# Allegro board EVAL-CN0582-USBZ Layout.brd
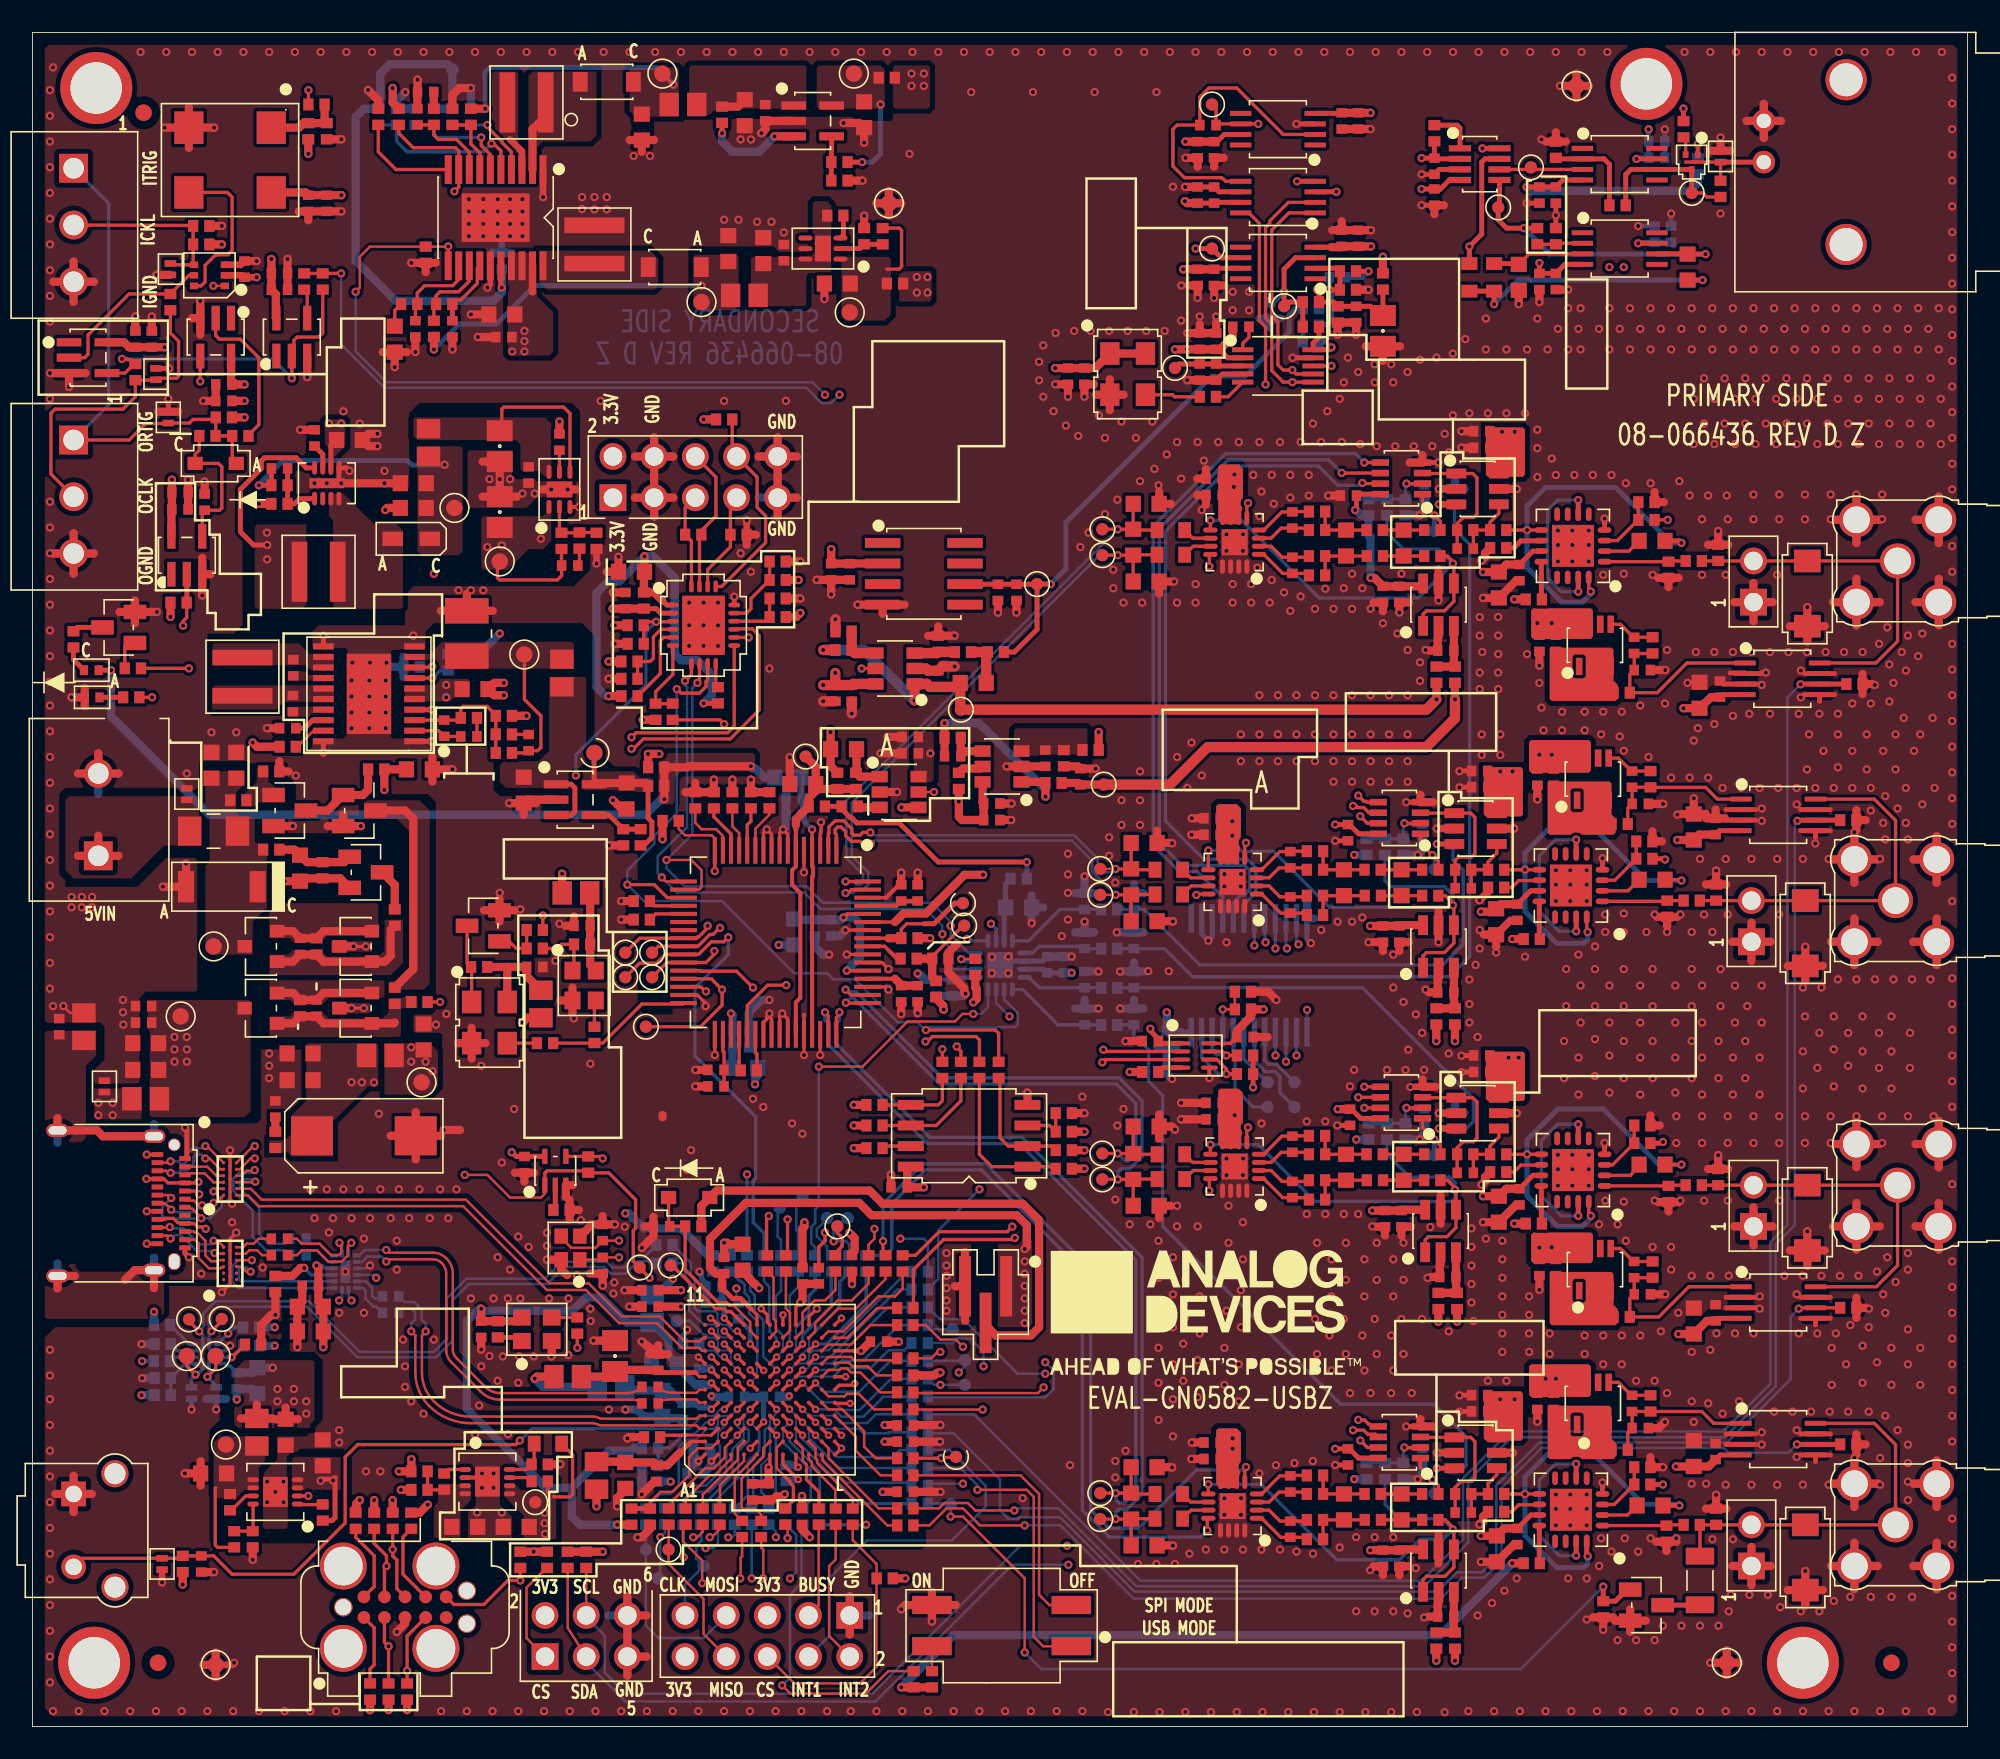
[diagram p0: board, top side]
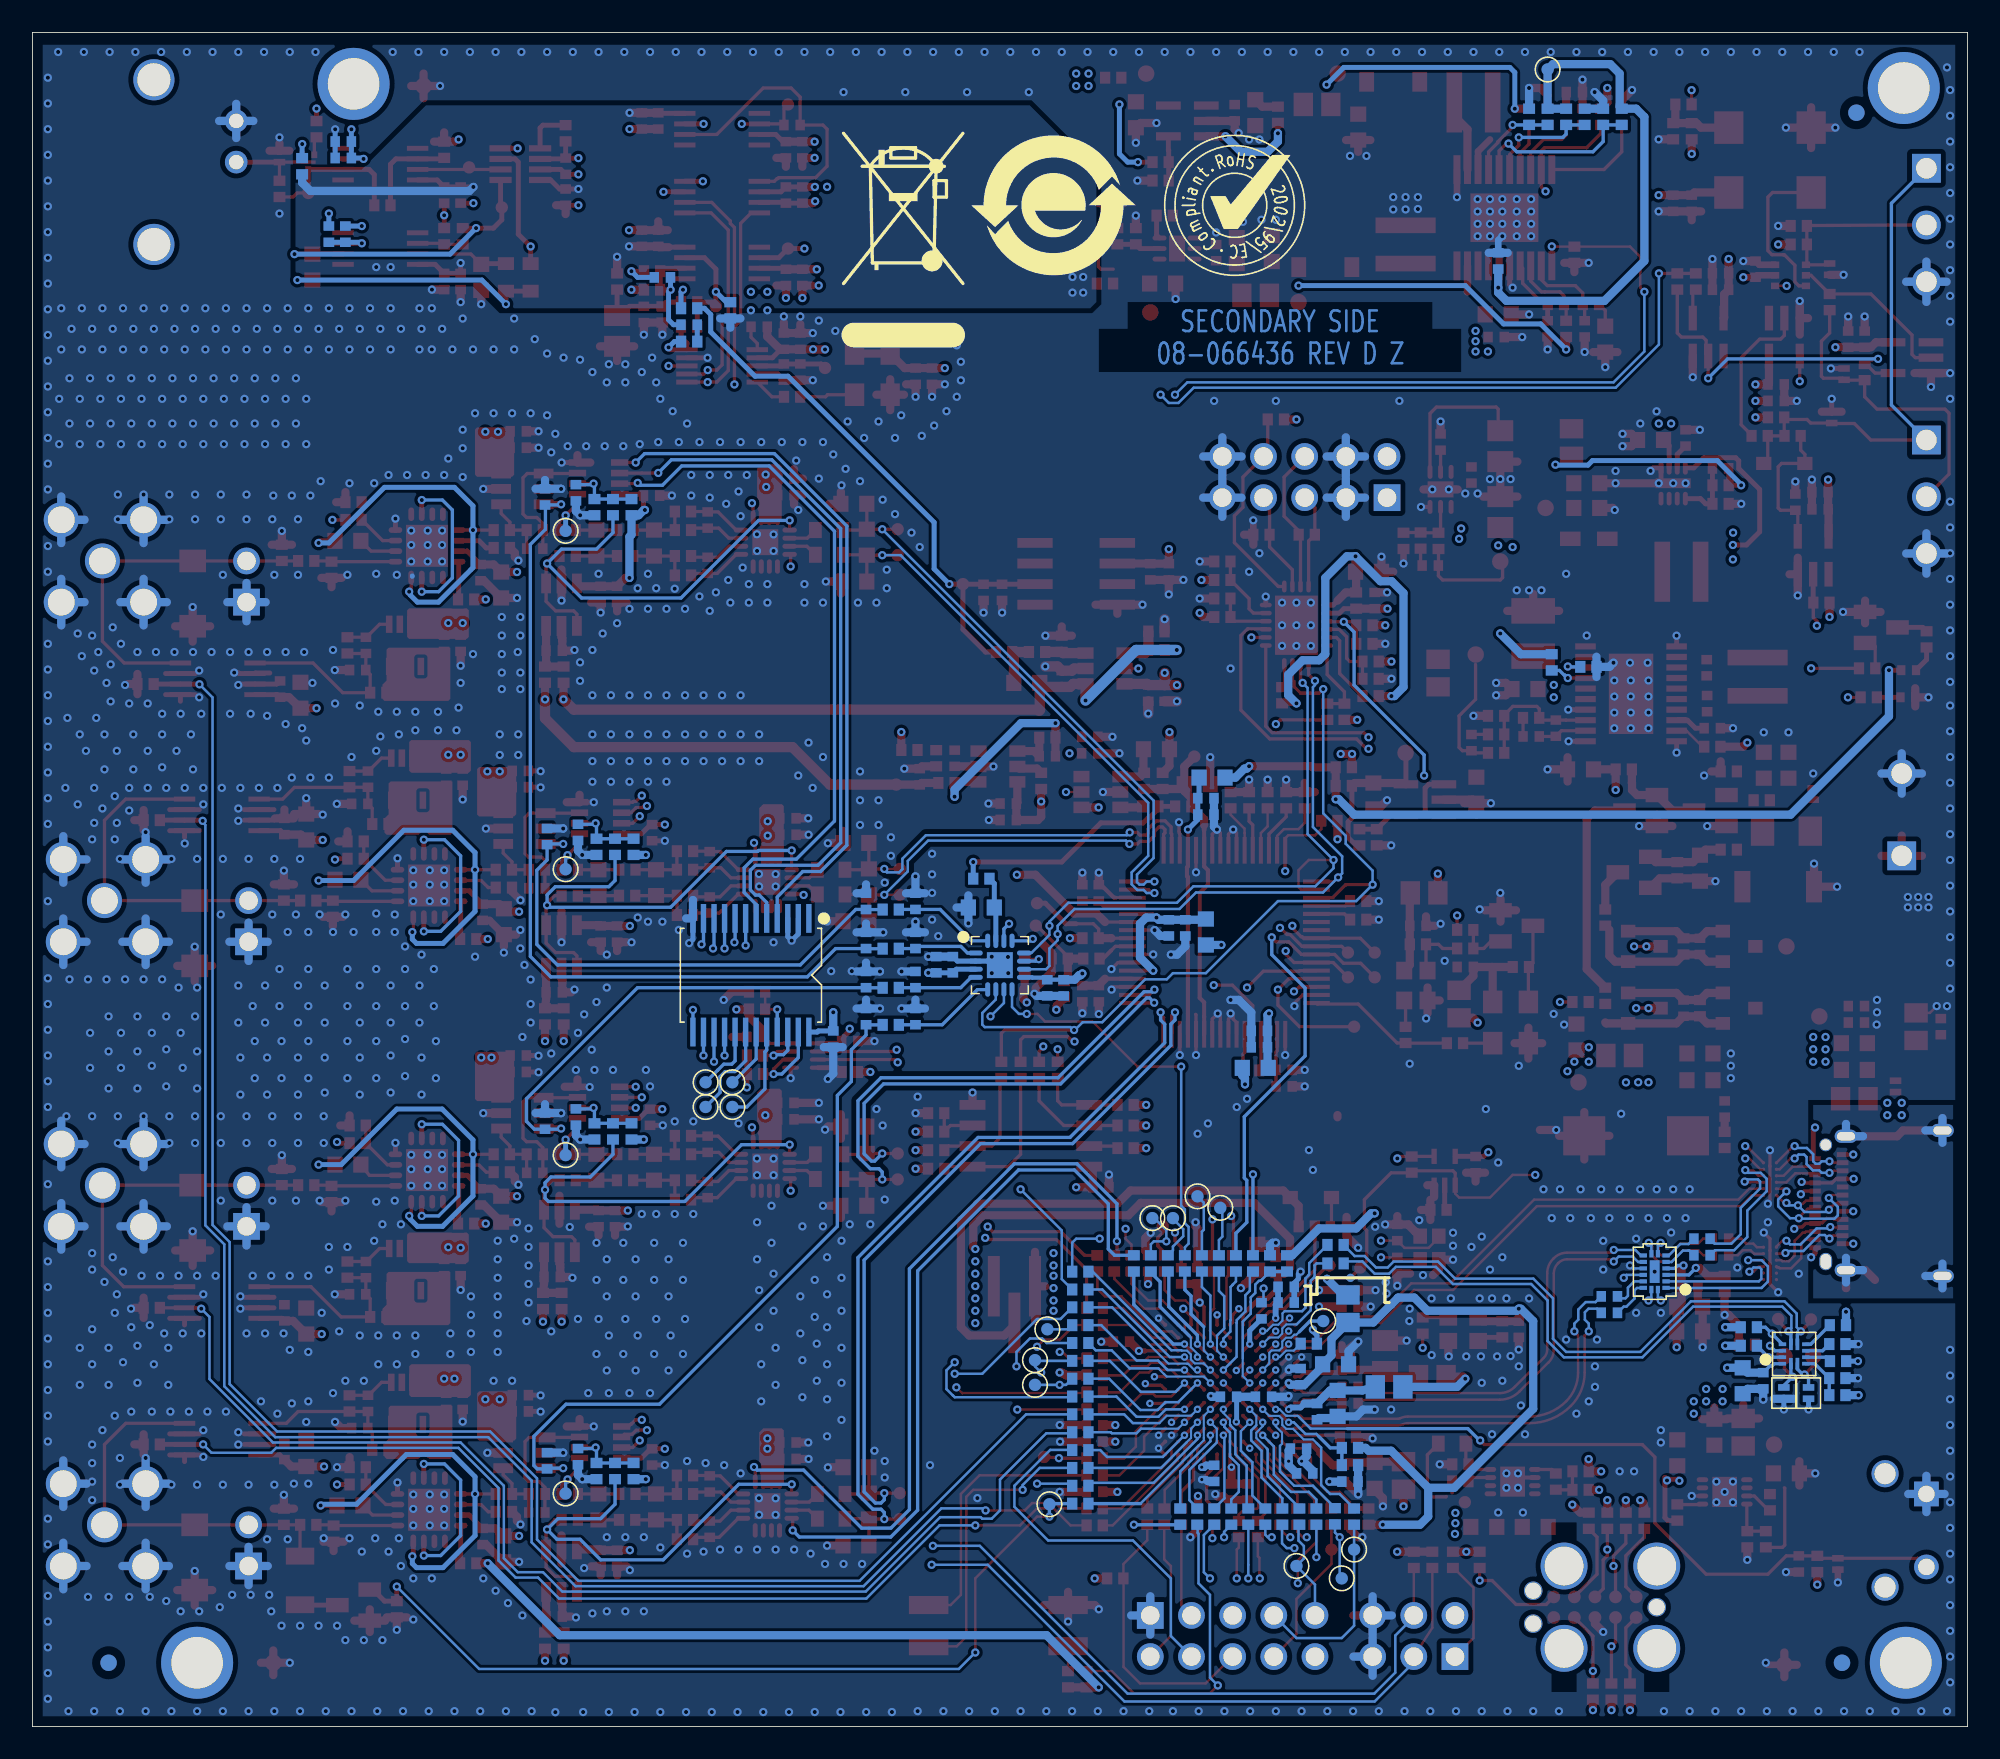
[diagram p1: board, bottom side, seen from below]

Outline 119.38 x 104.52 mm; copper layers: TOP, L2_GND, L3_SIG, L4_SIG, L5_GND, BOTTOM. Coordinates in mm from the lower left corner of the outline.
Outline path: 0,104.52 0,0 119.38,0 119.38,104.52 0,104.52

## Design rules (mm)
constraint set DEFAULT: min track width 0.152
net group CH0_OUT: nets CH0_OUT_N CH0_OUT_P
net group CH1_OUT: nets CH1_OUT_N CH1_OUT_P
net group CH2_OUT: nets CH2_OUT_N CH2_OUT_P
net group CH3_OUT: nets CH3_OUT_N CH3_OUT_P
net group CON_D: nets CON_DN CON_DP
net group CON_RX1: nets CON_RX1_N CON_RX1_P
net group CON_RX2: nets CON_RX2_N CON_RX2_P
net group CON_TX1: nets CON_TX1_N CON_TX1_P
net group CON_TX2: nets CON_TX2_N CON_TX2_P
net group DP1: nets SS_DM SS_DP
net group DP3: nets SS_TX_M SS_TX_P
net group DP4: nets UNNAMED_29_CAP_I53_N1 UNNAMED_29_CAP_I54_N1
net group RX1: nets RX1_N RX1_P
net group RX2: nets RX2_N RX2_P
net group SS_RX_M: nets SS_RX_M UNNAMED_29_CAP_I209_N2
net group SS_RX_P: nets SS_RX_P UNNAMED_29_CAP_I208_N2
net group TX1_N: nets TX1_N UNNAMED_22_CAP_I400_N1
net group TX1_P: nets TX1_P UNNAMED_22_CAP_I401_N1
net group TX2_N: nets TX2_N UNNAMED_22_CAP_I403_N1
net group TX2_P: nets TX2_P UNNAMED_22_CAP_I402_N1

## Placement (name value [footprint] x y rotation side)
A1  ADA4099-1HUJZ  [TSOT23_6]  89.15 37.85 270 top
A2  ADA4099-1HUJZ  [TSOT23_6]  89.03 16.89 270 top
A3  ADA4099-1HUJZ  [TSOT23_6]  89.15 76.36 270 top
A4  ADA4099-1HUJZ  [TSOT23_6]  89.03 55.4 270 top
A5  ADA4522-1ARMZ  [MSOP8]  97.92 91.19 270 top
A6  ADA4807-1ARJZ  [SOT23_6-2]  53.47 57.66 270 top
A7  ADA4522-1ARMZ  [MSOP8]  76.84 90.3 90 top
A8  ADA4522-1ARMZ  [MSOP8]  76.84 98.55 90 top
A9  ADA4807-1ARJZ  [SOT23_6-2]  53.21 65.28 90 top
A10  LTC6910-1HTS8#TRMPBF  [TSOT-8]  84.45 77.01 90 top
A11  LTC6910-1HTS8#TRMPBF  [TSOT-8]  84.33 56.05 90 top
A12  LTC6910-1HTS8#TRMPBF  [TSOT-8]  84.45 38.5 90 top
A13  LTC6910-1HTS8#TRMPBF  [TSOT-8]  84.33 17.54 90 top
A14  ADA4522-1ARMZ  [MSOP8]  97.92 96.39 270 top
A15  ADA4807-1ARJZ  [SOT23_6-2]  59.82 59.23 90 top
A16  ADA4099-1HUJZ  [TSOT23_6]  86.74 48.13 0 top
A17  ADA4099-1HUJZ  [TSOT23_6]  86.74 69.22 0 top
A18  ADA4099-1HUJZ  [TSOT23_6]  86.87 30.58 0 top
A19  ADA4099-1HUJZ  [TSOT23_6]  86.74 9.62 0 top
C1  0.1uF  [C0402]  1.65 43.18 90 top
C2  4.7uF  [C0603]  6.98 40.51 0 top
C3  1uF  [C0603]  6.98 42.16 0 top
C4  1000pF  [C0402]  64.91 48.5 270 bottom
C5  1000pF  [C0402]  64.91 46.09 270 bottom
C6  1000pF  [C0402]  67.95 48.5 270 bottom
C7  1000pF  [C0402]  67.95 46.09 270 bottom
C8  1000pF  [C0402]  64.91 43.8 270 bottom
C9  1000pF  [C0402]  64.91 50.91 270 bottom
C10  1000pF  [C0402]  67.95 43.8 270 bottom
C11  1000pF  [C0402]  67.95 50.91 270 bottom
C12  0.1uF  [C0402]  30.99 46.86 0 top
C13  0.1uF  [C0402]  33.91 49.4 180 top
C14  0.1uF  [C0402]  80.77 91.82 90 top
C15  10uF  [C0402]  81.79 91.82 270 top
C16  1uF  [C0402]  36.58 69.47 270 top
C17  4.7uF  [C0603]  36.96 71.25 180 top
C18  22uF  [C0603]  43.82 28.96 270 top
C19  0.1uF  [C0402]  38.1 26.92 180 top
C20  0.01uF  [C0402]  53.85 14.49 180 top
C21  0.01uF  [C0402]  38.1 25.91 0 top
C22  0.1uF  [C0402]  50.56 28.58 90 top
C23  0.01uF  [C0402]  46.48 15.62 90 bottom
C24  0.1uF  [C0402]  53.85 18.58 0 top
C25  0.1uF  [C0402]  92.96 28.32 270 top
C26  0.1uF  [C0402]  92.84 20.07 270 top
C27  10uF  [C0402]  98.81 28.19 90 top
C28  10uF  [C0402]  98.68 19.94 90 top
C29  0.1uF  [C0402]  93.98 28.32 270 top
C30  0.1uF  [C0402]  93.85 20.07 270 top
C31  0.1uF  [C0402]  99.31 26.67 0 top
C32  0.1uF  [C0402]  99.19 18.41 0 top
C33  68pF  [C0402]  88.39 34.16 180 top
C34  68pF  [C0402]  88.27 13.21 180 top
C35  0.1uF  [C0402]  89.41 40.39 180 top
C36  0.1uF  [C0402]  72.77 16.51 180 top
C37  1uF  [C0402]  89.41 41.4 180 top
C38  1uF  [C0402]  72.77 17.53 180 top
C39  1800pF  [C0603]  84.59 34.51 270 top
C40  1800pF  [C0603]  84.46 13.55 270 top
C41  1800pF  [C0603]  81.03 34.51 270 top
C42  1800pF  [C0603]  80.91 13.55 270 top
C43  1000pF  [C0402]  77.72 33.13 270 top
C44  1000pF  [C0402]  77.72 35.93 90 top
C45  1000pF  [C0402]  77.6 12.18 270 top
C46  1000pF  [C0402]  77.6 14.97 90 top
C47  0.1uF  [C0402]  72.9 37.46 180 top
C48  0.1uF  [C0402]  89.28 19.45 180 top
C49  1uF  [C0402]  72.9 38.48 180 top
C50  1uF  [C0402]  89.28 20.45 180 top
C51  1800pF  [C0603]  67.91 34.56 270 top
C52  1800pF  [C0603]  67.78 13.6 270 top
C53  100pF  [C0603]  68.71 32.13 180 top
C54  100pF  [C0603]  68.71 37.02 0 top
C55  100pF  [C0603]  68.58 11.18 180 top
C56  100pF  [C0603]  68.58 16 180 top
C57  0.1uF  [C0402]  92.96 66.83 270 top
C58  0.1uF  [C0402]  92.84 58.58 270 top
C59  10uF  [C0402]  98.81 66.71 90 top
C60  10uF  [C0402]  98.68 58.45 90 top
C61  0.1uF  [C0402]  93.98 66.83 270 top
C62  0.1uF  [C0402]  93.85 58.58 270 top
C63  0.1uF  [C0402]  99.31 65.18 0 top
C64  0.1uF  [C0402]  99.19 56.93 0 top
C65  68pF  [C0402]  88.39 72.67 180 top
C66  68pF  [C0402]  88.27 51.72 180 top
C67  0.1uF  [C0402]  81.18 75.95 180 top
C68  0.1uF  [C0402]  89.28 57.96 180 top
C69  1uF  [C0402]  72.9 76.99 180 top
C70  1uF  [C0402]  89.28 58.96 180 top
C71  1800pF  [C0603]  84.59 73.02 270 top
C72  1800pF  [C0603]  84.46 52.06 270 top
C73  1800pF  [C0603]  81.03 73.02 270 top
C74  1800pF  [C0603]  80.91 52.06 270 top
C75  1000pF  [C0402]  77.72 71.64 270 top
C76  1000pF  [C0402]  77.72 74.44 90 top
C77  1000pF  [C0402]  77.6 50.69 270 top
C78  1000pF  [C0402]  77.6 53.48 90 top
C79  0.1uF  [C0402]  89.41 78.9 180 top
C80  0.1uF  [C0402]  72.77 55.02 180 top
C81  1uF  [C0402]  89.41 79.91 180 top
C82  1uF  [C0402]  72.77 56.04 180 top
C83  1800pF  [C0603]  67.91 73.07 270 top
C84  1800pF  [C0603]  67.78 52.11 270 top
C85  100pF  [C0603]  68.71 70.64 180 top
C86  100pF  [C0603]  68.71 75.44 180 top
C87  100pF  [C0603]  68.58 49.69 180 top
C88  100pF  [C0603]  68.58 54.51 180 top
C89  0.1uF  [C0402]  30.61 77.22 270 top
C90  0.1uF  [C0402]  38.81 30.86 180 top
C91  2.2uF  [C0805H60]  28.83 78.99 270 top
C92  1000pF  [C0402]  32.51 79.25 270 top
C93  4.7uF  [C0603]  17.91 16.89 90 top
C94  4.7uF  [C0603]  11.18 15.62 180 top
C95  0.22uF  [C0402]  33.15 71.63 180 top
C96  2.2uF  [C0805H60]  28.83 74.93 90 top
C97  4.7uF  [C0603]  19.56 79.38 0 top
C98  1uF  [C0402]  28.96 90.42 270 bottom
C99  0.1uF  [C0402]  62.48 59.74 270 top
C100  1uF  [C0402]  17.4 79.5 270 top
C101  0.1uF  [C0402]  56.77 59.87 180 top
C102  0.1uF  [C0402]  59.18 56.95 0 top
C103  0.1uF  [C0402]  29.08 85.72 180 top
C104  10uF  [C0603]  28.96 87.12 0 top
C105  10uF  [C0402]  59.18 55.93 180 top
C106  4.7uF  [C0603]  23.49 75.18 0 top
C107  0.1uF  [C0402]  91.73 71.19 270 top
C108  1uF  [C0603]  23.49 76.71 0 top
C109  1200pF  [C0402]  23.75 99.31 90 top
C110  47pF  [C0402]  23.62 86.23 270 top
C111  1200pF  [C0402]  24.26 100.84 180 top
C112  6800pF  [C0603]  22.35 85.6 270 top
C113  1uF  [C0402]  25.91 86.23 90 top
C114  0.1uF  [C0402]  91.61 50.24 270 top
C115  10uF  [C0603]  90.46 70.43 90 top
C116  10uF  [C0603]  37.59 98.68 90 top
C117  10uF  [C0603]  42.93 91.19 270 top
C118  10uF  [C0603]  90.3 49.66 90 top
C119  22uF  [C0603]  99.92 73.15 180 top
C120  22uF  [C0603]  99.92 52.25 180 top
C121  0.1uF  [C0402]  91.73 32.68 270 top
C122  4.7uF  [C0603]  45.09 91.06 90 top
C123  4.7uF  [C0603]  43.94 99.57 270 top
C124  0.1uF  [C0402]  46.36 90.93 90 top
C125  0.1uF  [C0402]  45.21 99.57 270 top
C126  4.7uF  [C0603]  49.66 89.03 180 top
C127  0.1uF  [C0402]  91.61 11.73 270 top
C128  4.7uF  [C0603]  51.31 99.44 270 top
C129  10uF  [C0603]  90.46 31.92 90 top
C130  10uF  [C0603]  90.34 10.96 90 top
C131  22uF  [C0603]  99.92 34.67 180 top
C132  0.1uF  [C0402]  63.62 47 90 bottom
C133  1uF  [C0402]  62.6 47 90 bottom
C134  0.1uF  [C0402]  50.42 71.25 270 top
C135  0.1uF  [C0402]  43.56 25.65 90 bottom
C136  0.1uF  [C0402]  47.48 12.95 270 top
C137  1uF  [C0402]  49.28 71.25 270 top
C138  0.01uF  [C0402]  53.85 17.58 180 top
C139  0.1uF  [C0402]  38.1 15.11 180 bottom
C140  0.1uF  [C0402]  56.78 45.58 270 bottom
C141  0.1uF  [C0402]  38.1 20.96 180 top
C142  0.1uF  [C0402]  38.1 19.94 180 top
C143  1uF  [C0402]  55.76 45.58 270 bottom
C144  0.1uF  [C0402]  48.51 27.81 90 top
C145  0.1uF  [C0402]  59.56 69.98 270 top
C146  10uF  [C0603]  60.84 50.53 180 bottom
C147  0.1uF  [C0402]  52.2 23.74 0 top
C148  0.01uF  [C0402]  47.51 27.81 270 top
C149  22uF  [C0603]  38.86 19.94 90 bottom
C150  22uF  [C0603]  38.99 22.35 0 bottom
C151  0.1uF  [C0402]  44.41 14.48 270 top
C152  4.7uF  [C0603]  50.04 60.3 0 top
C153  22uF  [C0603]  99.79 13.64 180 top
C154  0.47uF  [C0603]  58.04 64.39 0 top
C155  0.01uF  [C0402]  45.41 14.48 90 top
C156  0.1uF  [C0402]  40.13 19.43 270 bottom
C157  22uF  [C0603]  47.52 58.14 0 top
C158  0.1uF  [C0402]  50.55 63.75 270 top
C159  0.1uF  [C0402]  54.15 60.05 180 top
C160  1uF  [C0402]  54.15 61.06 180 top
C161  0.1uF  [C0402]  41.15 21.59 90 bottom
C162  0.1uF  [C0402]  45.59 20.35 0 bottom
C163  0.1uF  [C0402]  46.99 56.26 180 bottom
C164  1uF  [C0402]  46.99 57.28 180 bottom
C165  0.1uF  [C0402]  49.28 49.28 270 bottom
C166  1uF  [C0402]  48.26 49.28 270 bottom
C167  0.1uF  [C0402]  43.69 41.91 180 bottom
C168  1uF  [C0402]  43.69 42.93 180 bottom
C169  0.1uF  [C0402]  42.16 40.51 180 top
C170  0.01uF  [C0402]  43.43 20.35 0 bottom
C171  1uF  [C0402]  42.16 39.5 180 top
C172  0.1uF  [C0402]  53.59 45.21 270 top
C173  1uF  [C0402]  54.61 45.21 270 top
C174  0.1uF  [C0402]  53.59 51.43 90 top
C175  1uF  [C0402]  54.61 51.43 90 top
C176  0.1uF  [C0402]  64.9 83.31 270 top
C177  0.1uF  [C0402]  72.01 85.47 90 top
C178  0.01uF  [C0402]  74.55 86.36 180 top
C179  10uF  [C0402]  73.03 85.47 270 top
C180  0.1uF  [C0402]  73.03 83.57 270 top
C181  10uF  [C0402]  72.01 83.57 90 top
C182  0.1uF  [C0402]  72.9 89.41 270 top
C183  10uF  [C0402]  71.88 89.41 90 top
C184  1uF  [C0402]  49.53 63.75 270 top
C185  1800pF  [C0603]  91.69 89.41 90 top
C186  0.1uF  [C0402]  93.98 89.15 270 top
C187  0.1uF  [C0402]  101.09 92.08 90 bottom
C188  10uF  [C0402]  92.96 89.15 90 top
C189  0.1uF  [C0402]  80.77 99.06 270 top
C190  10uF  [C0402]  100.08 92.08 270 bottom
C191  0.1uF  [C0402]  72.9 94.49 90 top
C192  10uF  [C0402]  71.88 94.49 270 top
C193  5.6pF  [C0402]  72.52 98.81 180 top
C194  0.1uF  [C0402]  41.28 17.14 180 bottom
C195  22uF  [C0603]  36.58 15.49 90 top
C196  2.2uF  [C0805H60]  35.94 22.86 90 top
C197  0.01uF  [C0402]  40.89 15.62 0 bottom
C198  0.1uF  [C0402]  38.48 15.62 270 top
C199  0.1uF  [C0402]  38.61 22.48 90 top
C200  0.1uF  [C0402]  42.04 26.16 180 bottom
C201  0.01uF  [C0402]  42.04 27.13 0 bottom
C202  15pF  [C0402]  35.18 28.45 270 top
C203  0.1uF  [C0402]  27.69 24.51 270 top
C204  15pF  [C0402]  35.18 30.48 90 top
C205  0.1uF  [C0402]  53.47 33.27 180 top
C206  0.1uF  [C0402]  10.41 10.03 270 top
C207  0.1uF  [C0402]  72.9 75.98 180 top
C208  4.7uF  [C0603]  26.67 12.32 180 top
C209  4.7uF  [C0603]  29.84 12.32 0 top
C210  0.1uF  [C0402]  81.15 55.15 270 top
C211  0.1uF  [C0402]  104.1 64.01 90 top
C212  0.1uF  [C0402]  103.84 55.53 90 top
C213  0.1uF  [C0402]  72.9 97.28 270 top
C214  10uF  [C0402]  81.79 99.06 90 top
C215  10uF  [C0402]  71.88 97.28 90 top
C216  1800pF  [C0603]  102.11 90.04 270 top
C217  10uF  [C0603]  27.3 64.01 180 top
C218  1uF  [C0402]  15.75 61.59 0 top
C219  0.1uF  [C0402]  16.07 63.11 270 top
C220  0.1uF  [C0402]  16.09 65.33 270 top
C221  680pF  [C0402]  26.92 61.09 0 top
C222  22pF  [C0402]  25.4 61.59 270 top
C223  47pF  [C0402]  30.61 60.71 270 top
C224  47uF  [C1210-2]  26.8 67.44 270 top
C225  4.7uF  [C0603]  30.31 57.77 270 top
C226  1uF  [C0402]  85.85 76.12 270 bottom
C227  4.7uF  [C0603]  36.66 57.41 270 top
C228  1uF  [C0402]  85.73 55.17 270 bottom
C229  0.1uF  [C0402]  81.28 37.59 270 top
C230  0.1uF  [C0402]  81.15 16.64 270 top
C231  1uF  [C0402]  85.85 37.61 270 bottom
C232  1uF  [C0402]  85.73 16.65 270 bottom
C233  0.1uF  [C0402]  69.98 42.42 270 bottom
C234  0.1uF  [C0402]  93.98 94.49 270 top
C235  0.1uF  [C0402]  100.2 96.77 0 bottom
C236  10uF  [C0402]  92.96 94.49 90 top
C237  10uF  [C0402]  100.2 97.79 180 bottom
C238  0.1uF  [C0402]  86.49 94.36 270 top
C239  0.1uF  [C0402]  86.49 96.27 270 top
C240  1000pF  [C0402]  10.62 75.54 270 top
C241  0.1uF  [C0402]  6.86 43.43 180 top
C242  1000pF  [C0402]  6.86 44.45 0 top
C243  2.2uF  [C0805H60]  83.31 86.11 90 top
C244  0.1uF  [C0402]  81.66 87.12 270 top
C245  0.1uF  [C0402]  11.81 82.8 180 top
C246  1uF  [C0402]  11.81 81.79 0 top
C247  4.7uF  [C0603]  11.05 59.31 270 top
C248  1uF  [C0603]  12.57 59.31 270 top
C249  10uF  [C0603]  102.84 63.63 90 top
C250  10uF  [C0603]  102.49 55.5 90 top
C251  0.1uF  [C0402]  16.38 29.08 0 bottom
C252  0.1uF  [C0402]  15.24 29.08 0 top
C253  0.1uF  [C0402]  16.38 30.1 0 bottom
C254  0.1uF  [C0402]  15.24 30.1 0 top
C255  0.1uF  [C0402]  17.14 27.18 180 top
C256  0.1uF  [C0402]  12.61 21.34 270 bottom
C257  4.7uF  [C0603]  17.14 24.38 0 top
C258  1uF  [C0603]  17.14 25.91 0 top
C259  1uF  [C0603]  13.88 21.34 90 bottom
C260  1uF  [C0603]  16.51 52.96 90 top
C261  0.1uF  [C0402]  17.53 44.32 270 top
C262  0.1uF  [C0402]  16.51 48.13 270 top
C263  10uF  [C0402]  87.76 75.87 90 bottom
C264  10uF  [C0402]  87.63 54.91 90 bottom
C265  10uF  [C0402]  87.76 37.35 90 bottom
C266  10uF  [C0402]  87.63 16.4 90 bottom
C267  0.01uF  [C0402]  63.88 83.31 90 top
C268  0.1uF  [C0402]  64.64 58.6 90 top
C269  1uF  [C0402]  60.71 69.98 270 top
C270  0.1uF  [C0402]  55.88 64.64 90 top
C271  0.1uF  [C0402]  22.1 26.54 0 bottom
C272  0.1uF  [C0402]  22.1 25.53 0 bottom
C273  0.1uF  [C0402]  18.16 93.98 270 top
C274  0.1uF  [C0402]  13.08 89.92 90 top
C275  0.1uF  [C0402]  6.35 85.6 90 top
C276  1uF  [C0402]  7.37 85.6 270 top
C277  4.7uF  [C0603]  15.62 18.16 270 top
C278  4.7uF  [C0603]  23.88 59.05 180 top
C279  10uF  [C0603]  16.51 39.88 0 top
C280  4.7uF  [C0603]  24.13 42.54 270 top
C281  0.1uF  [C0402]  68.96 42.29 180 top
C282  0.1uF  [C0402]  74.8 42.54 0 top
C283  0.1uF  [C0402]  42.67 28.45 90 top
C284  10uF  [C0603]  16.51 41.53 0 top
C285  0.1uF  [C0402]  9.1 75.1 0 top
C286  1uF  [C0402]  9.1 76.16 180 top
C287  0.1uF  [C0402]  14.99 38.1 90 top
C288  0.01uF  [C0402]  17.02 93.98 90 top
C289  0.1uF  [C0402]  15.24 88.65 0 top
C290  1uF  [C0402]  15.24 89.66 180 top
C291  10uF  [C0402]  78.87 86.49 180 bottom
C292  10pF  [C0402]  80.52 89.41 0 bottom
C293  100uF  [C7343]  20.45 36.45 0 top
C294  0.1uF  [C0402]  30.35 34.67 270 top
C295  0.1uF  [C0402]  103.84 25.53 90 top
C296  0.1uF  [C0402]  103.84 16.97 90 top
C297  10uF  [C0603]  102.49 25.02 90 top
C298  10uF  [C0603]  102.49 16.85 90 top
C299  0.1uF  [C0402]  84.33 48.89 270 top
C300  0.1uF  [C0402]  84.33 69.85 270 top
C301  0.1uF  [C0402]  84.45 31.34 270 top
C302  0.1uF  [C0402]  84.33 10.38 270 top
C303  1uF  [C0402]  83.31 69.85 270 top
C304  1uF  [C0402]  83.31 48.89 270 top
C305  1uF  [C0402]  83.31 10.38 270 top
C306  1uF  [C0402]  83.44 31.34 270 top
C307  10uF  [C0402]  87.19 66.38 180 top
C308  10uF  [C0402]  87.19 45.3 180 top
C309  10uF  [C0402]  87.19 6.79 180 top
C310  10uF  [C0402]  87.32 27.74 180 top
C311  4.7pF  [C0402]  15.24 77.62 0 top
CAP2.5  TESTPAD  [TPSMC30]  70.48 83.82 180 top
D1  PMEG3010BEA,115  [SOD323]  23.37 73.28 180 top
D2  MBR130LSFT1G  [SOD123FL]  35.43 101.47 180 top
D3  MBR130LSFT1G  [SOD123FL]  39.62 90.04 0 top
D4  BAV99QAZ  [SOT1215]  102.36 96.52 180 top
D5  D5V0H1B2LP-7B  [DFN2_1X0_6_NP_A]  104.14 96.87 270 top
D6  BAT54WS-E3  [SOD323-3]  40.51 32.64 0 top
D7  SMAJ40CA-TR  [DO214AC_C]  109.49 69.9 90 top
D8  BAT54WS-E3  [SOD323-3]  11.31 77.93 0 top
D9  SMAJ40CA-TR  [DO214AC_C]  109.37 48.94 90 top
D10  SMAJ40CA-TR  [DO214AC_C]  109.49 31.39 90 top
D11  SMAJ40CA-TR  [DO214AC_C]  109.37 10.43 90 top
D12  D5V0H1B2LP-7B  [DFN2_1X0_6_NP_A]  4.45 39.5 270 top
D13  D5V0H1B2LP-7B  [DFN2_1X0_6_NP_A]  8.38 80.77 270 top
D14  D5V0H1B2LP-7B  [DFN2_1X0_6_NP_A]  9.81 20.57 90 bottom
D15  D5V0H1B2LP-7B  [DFN2_1X0_6_NP_A]  11.34 20.57 90 bottom
D16  D5V0H1B2LP-7B  [DFN2_1X0_6_NP_A]  9.53 57.53 270 top
D17  D5V0H1B2LP-7B  [DFN2_1X0_6_NP_A]  8 10.03 90 top
D18  PMEG3050EP,115  [SOD128]  11.68 51.82 180 top
D19  D5V0H1B2LP-7B  [DFN2_1X0_6_NP_A]  8.51 89.92 90 top
D20  D5V0H1B2LP-7B  [DFN2_1X0_6_NP_A]  7.62 83.44 270 top
DS1  SML-P11MTT86R  [LED0402]  3.68 63.5 0 top
DS2  SML-P11VTT86  [LED0402]  3.63 65.17 0 top
E1  220 OHM AT 100MEGHZ  [L0805]  3.17 43.18 90 top
E2  1000OHM AT 100MEGHz  [L0603]  46.61 58.55 0 bottom
E3  1000OHM AT 100MEGHz  [L0603]  46.99 49.02 90 bottom
E4  1000OHM AT 100MEGHz  [L0603]  43.94 40.64 0 bottom
E5  220 OHM AT 100MEGHZ  [L0805]  6.98 38.73 0 top
E6  600OHM AT 100MEGHZ  [L0805]  35.69 20.96 180 bottom
E7  600OHM AT 100MEGHZ  [L0805]  38.23 25.78 90 bottom
E8  600OHM AT 100MEGHZ  [L0805]  34.8 15.49 270 top
E9  600OHM AT 100MEGHZ  [L0805]  33.02 21.59 180 top
E10  220 OHM AT 100MEGHZ  [L0805]  40.13 100.08 0 top
E11  220 OHM AT 100MEGHZ  [L0805]  43.92 88.3 0 top
E12  220 OHM AT 100MEGHZ  [L0805]  24.44 79.22 90 top
E13  220 OHM AT 100MEGHZ  [L0805]  21.46 41.4 0 top
E14  220 OHM AT 100MEGHZ  [L0805]  32.66 65 270 top
E15  220 OHM AT 100MEGHZ  [L0805]  13.84 18.16 90 top
E16  220 OHM AT 100MEGHZ  [L0805]  31.37 44.58 90 top
E17  220 OHM AT 100MEGHZ  [L0805]  33.53 51.43 0 top
F1  2A  [F1206H46]  11.18 55.24 0 top
FL1  PCMF3USB30Z  [WLCSP15H22]  12.19 33.78 0 top
FL2  PCMF3USB30Z  [WLCSP15H22]  12.19 28.58 0 top
J1  SMA-J-P-H-RA-TH1  [CNSMARAL594W276H393]  115.06 71.91 0 top
J2  SMA-J-P-H-RA-TH1  [CNSMARAL594W276H393]  114.94 50.96 0 top
J3  SMA-J-P-H-RA-TH1  [CNSMARAL594W276H393]  115.06 33.4 0 top
J4  SMA-J-P-H-RA-TH1  [CNSMARAL594W276H393]  114.94 12.45 0 top
J6  227161-1  [CNAMP227161-1]  106.81 96.52 0 top
L1  6.8uH  [LSMSQ157H122]  17.65 71.25 180 top
L2  4.7uH  [LSMSQ157H122]  30.48 100.2 180 top
L3  8.2UH  [LSMSQ157H161]  34.67 91.44 90 top
L4  4.7uH  [LSMSQ157H122]  12.95 64.77 270 top
M1  12401598E4#2A  [M12401598E4_2A]  4.41 32.29 270 top
NOREF  -  [unnamed]  6.86 99.57 0 top
NOREF#2  -  [#2]  3.81 3.94 0 top
NOREF#3  -  [unnamed]  109.22 3.94 0 top
NOREF#4  -  [unnamed]  99.57 101.35 0 top
NOREF#5  -  [#2]  119.51 0 90 top
NOREF#6  -  [#2]  3.81 3.94 0 top
NOREF#7  -  [#2]  -111.76 -103.5 0 top
NOREF#8  -  [#2]  267.17 120.33 0 top
NOREF#9  -  [unnamed]  3.81 3.94 0 top
NOREF#10  -  [unnamed]  3.94 101.09 0 top
NOREF#11  -  [#2]  0 104.52 270 top
NOREF#12  -  [#2]  119.51 104.52 180 top
NOREF#13  -  [#2]  0 0 0 top
NOREF#14  -  [#2]  -73.66 222.89 0 top
NOREF#15  -  [#2]  -111.76 -103.5 0 top
NOREF#16  -  [#2]  -50.8 267.34 0 top
NOREF#17  -  [#2]  -111.76 -103.5 0 top
NOREF#18  -  [#2]  119.38 0 0 top
NOREF#19  -  [#2]  308.86 378.71 0 top
NOREF#20  -  [#2]  29.87 25.51 0 top
NOREF#21  -  [#2]  0 0 0 top
NOREF#22  -  [#2]  43.05 72.26 270 top
NOREF#23  -  [#2]  -111.76 -103.5 0 top
NOREF#24  -  [#2]  -60.96 38.73 0 top
NOREF#25  -  [#2]  348.63 121.51 0 top
NOREF#26  -  [#2]  119.38 0 90 top
NOREF#27  -  [#2]  0 104.52 0 top
NOREF#28  -  [#2]  0 0 0 top
NOREF#29  -  [unnamed]  7.75 3.94 0 top
NOREF#30  -  [#2]  32.4 30.51 0 top
NOREF#31  -  [unnamed]  114.68 3.94 0 top
NOREF#32  -  [#2]  0 104.52 0 top
NOREF#33  -  [#2]  165.61 127.25 0 top
NOREF#34  -  [#2]  72.39 25.53 0 top
NOREF#35  -  [unnamed]  6.86 99.57 180 bottom
NOREF#36  -  [#2]  56.39 101.98 180 bottom
NOREF#37  -  [unnamed]  7.75 3.94 0 bottom
NOREF#38  -  [#2]  56.39 93.85 180 bottom
NOREF#39  -  [#2]  45.21 93.85 180 bottom
NOREF#40  -  [unnamed]  114.68 3.94 0 bottom
P1  TSW-102-07-G-S  [CNTHMHDR1X2L200W98H343]  106.17 69.37 90 top
P2  TSW-102-07-G-S  [CNTHMHDR1X2L200W98H343]  106.05 48.42 90 top
P3  TSW-102-07-G-S  [CNTHMHDR1X2L200W98H343]  106.17 30.86 90 top
P4  TSW-102-07-G-S  [CNTHMHDR1X2L200W98H343]  106.05 9.91 90 top
P5  1751251  [CNPHOENIX1751251]  2.54 96.14 270 top
P7  TC2050-IDC  [CNTC2050-IDC]  22.99 7.37 0 top
P8  TESTPAD3P  [TP3SM29X147]  58.8 26.04 180 top
P9  TSW-105-07-T-D  [CNSAMTEC2X5H338LD36]  50.42 6.86 180 top
P10  TSW-103-08-T-D  [CNSAMTEC2X3H330LD36]  31.62 4.32 0 top
P11  TSW-105-07-T-D  [CNSAMTEC2X5H338LD36]  35.81 75.82 0 top
P12  EDZ250/2  [CNTH1X2H394]  4.06 53.72 90 top
P14  1751251  [CNPHOENIX1751251]  2.54 79.38 270 top
Q1  DMN2005K-7  [SOT23-2]  15.88 56.52 270 top
Q2  DMN2005K-7  [SOT23-2]  5.32 67.81 90 top
Q3  DMN2005K-7  [SOT23-2]  20.16 56.52 270 top
Q4  DMN2005K-7  [SOT23-2]  20.57 52.7 270 top
Q5  IRLML6401TRPBF  [SOT23-M3]  14.1 44.32 90 top
Q6  IRLML6401TRPBF  [SOT23-M3]  14.1 48.13 90 top
Q7  IRLML6401TRPBF  [SOT23-M3]  19.94 44.32 90 top
Q8  IRLML6401TRPBF  [SOT23-M3]  19.94 48.13 90 top
Q9  DMN2005K-7  [SOT23-2]  99.57 7.49 270 top
Q10  DMN2005K-7  [SOT23-2]  27.81 49.4 90 top
R1  10K  [R0402]  13.49 23.5 0 bottom
R2  1K  [R0402]  66.43 47.99 0 bottom
R3  1K  [R0402]  66.43 45.58 0 bottom
R4  1K  [R0402]  66.43 43.29 0 bottom
R5  1K  [R0402]  66.43 50.41 0 bottom
R6  10K  [R0402]  27.56 46.86 180 top
R7  0  [R0402]  86.61 64.9 90 top
R8  0  [R0402]  38.48 59.18 0 top
R9  120K  [R0402]  99.95 28.19 90 top
R10  120K  [R0402]  99.82 19.94 90 top
R11  100K  [R0402]  103.99 33.9 270 top
R12  100K  [R0402]  103.87 12.95 270 top
R13  0  [R0402]  102.49 33.4 180 top
R14  0  [R0402]  102.36 12.45 180 top
R15  100K  [R0402]  100.93 32.86 90 top
R16  100K  [R0402]  100.8 11.9 90 top
R17  300  [R0402]  98.04 25.27 180 top
R18  300  [R0402]  97.92 17.07 180 top
R19  49.9K  [R0402]  90.42 35.31 180 top
R20  49.9K  [R0402]  90.3 14.35 180 top
R21  15K  [R0402]  88.39 35.31 180 top
R22  15K  [R0402]  88.27 14.35 180 top
R23  0  [R0402]  86.36 35.31 180 top
R24  0  [R0402]  86.23 14.35 180 top
R25  0  [R0402]  86.36 33.71 180 top
R26  0  [R0402]  86.23 12.75 180 top
R27  750  [R0402]  82.82 33.71 180 top
R28  750  [R0402]  82.8 35.31 180 top
R29  750  [R0402]  82.69 12.75 180 top
R30  750  [R0402]  82.68 14.35 180 top
R31  374  [R0402]  79.25 33.71 180 top
R32  374  [R0402]  79.25 35.31 180 top
R33  374  [R0402]  79.12 12.75 180 top
R34  374  [R0402]  79.12 14.35 180 top
R35  2K  [R0402]  79.25 32.51 180 top
R36  2K  [R0402]  79.25 36.45 180 top
R37  2K  [R0402]  79.12 11.56 180 top
R38  2K  [R0402]  79.12 15.49 180 top
R39  82.5  [R0603]  70.23 33.78 180 top
R40  82.5  [R0603]  70.23 35.31 180 top
R41  82.5  [R0603]  70.1 12.83 180 top
R42  82.5  [R0603]  70.1 14.35 180 top
R43  120K  [R0402]  99.95 66.71 90 top
R44  120K  [R0402]  99.82 58.45 90 top
R45  100K  [R0402]  103.99 72.41 270 top
R46  100K  [R0402]  103.87 51.46 270 top
R47  0  [R0402]  102.49 71.91 180 top
R48  0  [R0402]  102.36 50.96 180 top
R49  100K  [R0402]  100.93 71.37 90 top
R50  100K  [R0402]  100.85 50.46 90 top
R51  300  [R0402]  98.04 63.78 180 top
R52  300  [R0402]  97.92 55.68 180 top
R53  49.9K  [R0402]  90.42 73.82 180 top
R54  49.9K  [R0402]  90.3 52.86 180 top
R55  15K  [R0402]  88.39 73.82 180 top
R56  15K  [R0402]  88.27 52.86 180 top
R57  0  [R0402]  86.36 73.82 180 top
R58  0  [R0402]  86.23 52.86 180 top
R59  0  [R0402]  86.36 72.22 180 top
R60  0  [R0402]  86.23 51.26 180 top
R61  750  [R0402]  82.82 72.22 180 top
R62  750  [R0402]  82.8 73.82 180 top
R63  750  [R0402]  82.69 51.26 180 top
R64  750  [R0402]  82.68 52.86 180 top
R65  374  [R0402]  79.25 72.22 180 top
R66  374  [R0402]  79.25 73.82 180 top
R67  374  [R0402]  79.12 51.26 180 top
R68  374  [R0402]  79.12 52.86 180 top
R69  2K  [R0402]  79.25 71.02 180 top
R70  2K  [R0402]  79.25 74.96 180 top
R71  2K  [R0402]  79.12 50.07 180 top
R72  2K  [R0402]  79.12 54.01 180 top
R73  82.5  [R0603]  70.23 72.29 180 top
R74  82.5  [R0603]  70.23 73.82 180 top
R75  82.5  [R0603]  70.1 51.34 180 top
R76  82.5  [R0603]  70.1 52.86 180 top
R77  10K  [R0402]  33.91 48.26 180 top
R78  0  [R0402]  87.76 64.9 90 top
R79  10K  [R0402]  13.49 24.64 0 bottom
R80  332K  [R0402]  32.64 73.15 270 top
R81  16K  [R0402]  34.8 73.15 90 top
R82  0  [R0402]  21.34 99.31 90 bottom
R83  0  [R0402]  22.48 99.31 270 bottom
R84  0  [R0402]  24.76 99.31 90 bottom
R85  0  [R0402]  23.62 99.31 270 bottom
R86  0  [R0402]  25.91 99.31 90 bottom
R87  0  [R0402]  27.05 99.31 270 bottom
R88  0  [R0402]  48.39 56.77 180 top
R89  10K  [R0402]  22.61 99.31 90 top
R90  1MEG  [R0402]  15.24 76.58 180 top
R91  63.4K  [R0402]  15.24 75.44 0 top
R92  28K  [R0402]  24.76 99.31 90 top
R93  6.49K  [R0402]  25.4 87.76 180 top
R94  7.32K  [R0402]  23.24 87.76 180 top
R95  90.9K  [R0402]  24.76 86.23 270 top
R96  4.75K  [R0402]  25.91 99.31 270 top
R97  57.6K  [R0402]  27.05 99.31 90 top
R98  10K  [R0402]  24.26 90.8 90 top
R99  0  [R0402]  93.98 91.95 270 top
R100  10K  [R0402]  8.03 20.45 180 bottom
R101  10K  [R0402]  7.99 22.55 180 bottom
R102  0  [R0402]  17.91 13.21 90 top
R103  0  [R0402]  42.55 99.44 90 top
R104  0  [R0402]  49.53 93.22 180 top
R105  107K  [R0402]  51.31 91.95 90 top
R106  332K  [R0402]  52.45 91.95 90 top
R107  47K  [R0402]  12.45 11.56 270 top
R108  15K  [R0402]  13.59 11.56 90 top
R109  0  [R0402]  49.78 96.52 0 top
R110  243K  [R0402]  49.78 95.38 0 top
R111  1K  [R0402]  6.1 63.5 0 top
R112  0  [R0402]  92.84 91.95 270 top
R113  0  [R0402]  12.19 13.84 270 top
R114  10K  [R0402]  13.61 23.57 0 top
R115  0  [R0402]  52.71 101.73 180 top
R116  0  [R0402]  53.21 89.03 180 top
R117  0  [R0402]  65.28 60.25 180 top
R118  22  [R0402]  45.34 28.58 270 top
R119  22  [R0402]  45.13 28.58 270 bottom
R120  22  [R0402]  44.08 28.58 270 bottom
R121  0  [R0402]  102.74 96.27 90 bottom
R122  22  [R0402]  47.23 28.58 270 bottom
R123  22  [R0402]  46.18 28.58 270 bottom
R124  22  [R0402]  49.53 28.58 270 top
R125  22  [R0402]  49.33 28.58 270 bottom
R126  22  [R0402]  51.58 28.58 270 top
R127  22  [R0402]  51.44 28.58 270 bottom
R128  0  [R0402]  60.84 52.31 0 bottom
R129  22  [R0402]  52.63 28.58 270 top
R130  22  [R0402]  53.85 25.82 180 top
R131  3.3K  [R0402]  59.44 66.29 180 top
R132  1K  [R0402]  50.42 56.77 0 top
R133  22  [R0402]  53.68 28.58 270 top
R134  22  [R0402]  53.85 24.77 180 top
R135  3.3K  [R0402]  57.4 66.29 180 top
R136  22  [R0402]  54.74 26.97 180 bottom
R137  22  [R0402]  48.28 28.58 270 bottom
R138  100  [R0402]  50.8 58.34 270 top
R139  1K  [R0402]  49.66 58.34 270 top
R140  22  [R0402]  54.74 22.56 180 bottom
R141  22  [R0402]  53.85 22.72 180 top
R142  100  [R0402]  50.04 66.42 180 top
R143  4.7K  [R0402]  50.04 67.56 0 top
R144  22  [R0402]  53.85 20.62 180 top
R145  22  [R0402]  54.74 24.76 180 bottom
R146  22  [R0402]  54.74 25.87 180 bottom
R147  22  [R0402]  54.74 28.07 180 bottom
R148  2K  [R0402]  80.52 87.12 90 top
R149  10K  [R0402]  54.1 48.64 180 top
R150  1K  [R0402]  37.59 49.78 0 top
R151  0  [R0402]  44.19 40.48 0 top
R152  22  [R0402]  54.74 23.66 180 bottom
R153  0  [R0402]  72.52 82.04 180 top
R154  1K  [R0402]  78.87 86.36 180 top
R155  249  [R0402]  81.15 88.65 180 top
R156  102K  [R0402]  81.15 89.79 0 top
R157  1K  [R0402]  78.87 87.88 180 top
R158  0  [R0402]  37.52 54.86 90 top
R159  3.4K  [R0603]  88.65 89.41 270 top
R160  3.4K  [R0603]  90.17 89.41 90 top
R161  22  [R0402]  54.74 17.06 0 bottom
R162  22  [R0402]  50.38 28.58 270 bottom
R163  22  [R0402]  54.74 13.76 180 bottom
R164  22  [R0402]  54.74 21.46 180 bottom
R165  22  [R0402]  53.85 16.55 180 top
R166  22  [R0402]  54.74 20.36 180 bottom
R167  200  [R0402]  38.23 17.86 0 top
R168  22  [R0402]  47.52 12.95 270 bottom
R169  22  [R0402]  54.74 15.96 0 bottom
R170  22  [R0402]  53.85 15.5 0 top
R171  22  [R0402]  43.32 12.95 270 bottom
R172  22  [R0402]  42.4 12.95 270 top
R173  22  [R0402]  41.35 12.95 270 top
R174  22  [R0402]  41.22 12.95 270 bottom
R175  22  [R0402]  40.3 12.95 270 top
R176  22  [R0402]  39.25 12.95 270 top
R177  22  [R0402]  37.85 12.95 270 bottom
R178  6.04K  [R0402]  40.64 23.62 0 bottom
R179  10K  [R0402]  53.85 21.67 0 top
R180  0  [R0402]  28.7 24.51 270 top
R181  1K  [R0402]  6.2 65.29 180 top
R182  3.3K  [R0402]  2.53 67.08 90 top
R183  33  [R0402]  33.61 24.74 270 top
R184  10K  [R0402]  36.96 12.95 270 top
R185  10K  [R0402]  38.1 12.95 90 top
R186  10K  [R0402]  38.1 17.2 180 bottom
R187  10K  [R0402]  38.1 16.13 0 bottom
R188  10K  [R0402]  41.98 28.58 90 bottom
R189  10K  [R0402]  43.03 28.58 270 bottom
R190  0  [R0402]  63.63 59.74 90 top
R191  10K  [R0402]  55.5 2.92 270 top
R192  10K  [R0402]  54.36 2.92 270 top
R193  4.7K  [R0402]  63.63 34.42 0 top
R194  4.7K  [R0402]  63.63 36.7 0 top
R195  0  [R0402]  56.77 61.01 0 top
R196  10K  [R0402]  19.94 12.7 90 top
R197  100K  [R0402]  63.63 35.56 180 top
R198  10K  [R0402]  63.63 37.85 180 top
R199  10K  [R0402]  21.08 12.7 90 top
R200  10K  [R0402]  22.22 12.7 90 top
R201  0  [R0402]  56.13 40.51 270 top
R202  0  [R0402]  59.61 40.51 270 top
R203  0  [R0402]  57.28 40.51 270 top
R204  0  [R0402]  58.42 40.51 270 top
R205  10K  [R0402]  23.37 12.7 90 top
R206  10K  [R0402]  30.1 10.29 90 top
R207  10K  [R0402]  23.11 2.16 270 top
R208  100K  [R0402]  9.27 10.03 90 top
R209  100K  [R0402]  51.94 35.69 0 top
R210  100K  [R0402]  51.94 38.35 0 top
R211  4.7K  [R0402]  51.94 37.08 180 top
R212  22  [R0402]  49.55 12.95 270 top
R213  22  [R0402]  48.5 12.95 270 top
R214  22  [R0402]  54.74 14.86 0 bottom
R215  22  [R0402]  45.42 12.95 270 bottom
R216  22  [R0402]  46.44 12.95 270 top
R217  22  [R0402]  48.57 12.95 270 bottom
R218  22  [R0402]  46.47 12.95 270 bottom
R219  22  [R0402]  42.27 12.95 270 bottom
R220  22  [R0402]  53.85 13.46 0 top
R221  22  [R0402]  54.74 18.16 0 bottom
R222  22  [R0402]  53.85 12.41 0 top
R223  22  [R0402]  50.6 12.95 270 top
R224  0  [R0402]  25.4 15.11 270 top
R225  0  [R0402]  31.29 15.13 180 top
R226  5.1K  [R0603]  31.8 17.45 0 top
R227  10K  [R0402]  31.29 16.18 0 top
R228  0  [R0402]  101.85 98.55 270 top
R229  10K  [R0402]  21.97 2.16 270 top
R230  0  [R0402]  20.83 2.16 270 top
R231  0  [R0402]  40.77 30.86 180 top
R232  22  [R0402]  44.37 12.95 270 bottom
R233  22  [R0402]  43.78 12.19 270 top
R234  0  [R0402]  38.99 28.58 180 bottom
R235  0  [R0402]  38.99 29.72 180 bottom
R236  0  [R0402]  31.75 10.29 90 top
R237  4.7K  [R0402]  33.02 10.29 270 top
R238  4.7K  [R0402]  34.16 10.29 270 top
R239  0  [R0402]  36.83 64.64 180 top
R240  1K  [R0402]  45.97 70.74 0 top
R241  1K  [R0402]  45.97 71.88 180 top
R242  1K  [R0402]  45.97 68.45 0 top
R243  1K  [R0402]  45.97 69.6 180 top
R244  1K  [R0402]  36.83 65.71 180 top
R245  0  [R0402]  39.5 62.61 90 top
R246  1K  [R0402]  37.21 67.94 180 top
R247  0  [R0402]  37.72 69.47 270 top
R248  10K  [R0402]  42.29 63.63 270 top
R249  4.7K  [R0402]  36.83 63.58 0 top
R250  619  [R0402]  42.67 80.64 0 top
R251  619  [R0402]  43.56 73.53 0 top
R252  120  [R0402]  40.77 73.53 0 top
R253  0  [R0402]  62.99 58.22 0 top
R254  10.5K  [R0402]  55.88 66.8 90 top
R255  0  [R0402]  55.74 45.5 90 top
R256  0  [R0402]  56.01 47.38 0 top
R257  10K  [R0402]  54.05 47.38 180 top
R258  10K  [R0402]  37.59 50.93 180 top
R259  10K  [R0402]  45.47 57.15 270 top
R260  10K  [R0402]  40.89 57.15 270 top
R261  10K  [R0402]  42.04 57.15 270 top
R262  10K  [R0402]  43.18 57.15 270 top
R263  10K  [R0402]  44.32 57.15 270 top
R264  0  [R0402]  86.61 43.81 90 top
R265  0  [R0402]  87.76 43.81 90 top
R266  0  [R0402]  86.61 5.3 90 top
R267  0  [R0402]  87.76 5.3 90 top
R268  22  [R0402]  46.48 28.58 270 top
R269  22  [R0402]  53.85 19.57 180 top
R270  22  [R0402]  39.03 12.98 270 bottom
R271  22  [R0402]  54.74 19.26 0 bottom
R272  22  [R0402]  44.96 12.19 270 top
R273  22  [R0402]  40.17 12.95 270 bottom
R274  0  [R0402]  23.88 15.75 180 top
R275  0  [R0402]  23.88 14.6 180 top
R276  0  [R0402]  21.34 99.31 270 top
R277  1K  [R0402]  33.74 73.17 270 top
R278  0  [R0402]  36.45 54.86 270 top
R279  0  [R0402]  92.62 69.54 0 top
R280  0  [R0402]  92.5 48.59 0 top
R281  499K  [R0402]  90.42 72.72 0 top
R282  499K  [R0402]  90.3 51.76 0 top
R283  0  [R0402]  92.62 31.03 0 top
R284  0  [R0402]  92.5 10.08 0 top
R285  499K  [R0402]  90.42 34.21 0 top
R286  499K  [R0402]  90.3 13.25 0 top
R287  10K  [R0402]  25.65 65.66 90 bottom
R288  33K  [R0402]  26.92 62.23 0 top
R289  845K  [R0402]  29.08 60.07 0 top
R290  120K  [R0402]  29.08 62.36 180 top
R291  10K  [R0402]  29.08 61.21 180 top
R292  10K  [R0402]  8.03 21.5 0 bottom
R293  0  [R0402]  38.48 58.04 180 top
R294  10K  [R0402]  15.75 60.45 180 top
R295  42.2K  [R0402]  23.39 65.38 180 bottom
R296  10K  [R0402]  14.99 27.3 90 top
R297  100K  [R0402]  21.21 59.05 180 top
R298  100  [R0402]  83.57 75.23 270 bottom
R299  100  [R0402]  83.44 54.28 270 bottom
R300  100  [R0402]  83.57 36.72 270 bottom
R301  100  [R0402]  83.44 15.76 270 bottom
R302  17.4K  [R0402]  84.71 75.23 90 bottom
R303  17.4K  [R0402]  84.58 54.28 90 bottom
R304  17.4K  [R0402]  82.42 75.23 270 bottom
R305  17.4K  [R0402]  82.3 54.28 270 bottom
R306  17.4K  [R0402]  84.58 15.76 90 bottom
R307  17.4K  [R0402]  84.71 36.72 90 bottom
R308  17.4K  [R0402]  82.3 15.76 270 bottom
R309  17.4K  [R0402]  82.42 36.72 270 bottom
R310  10K  [R0402]  86.49 98.3 90 top
R311  10.5K  [R0402]  83.31 89.15 90 top
R312  1K  [R0402]  97.79 93.85 0 top
R313  10K  [R0402]  9.02 69.34 0 top
R314  1K  [R0402]  12.83 79.63 180 top
R315  10K  [R0402]  11.81 80.77 0 top
R316  10K  [R0402]  8.03 23.6 0 bottom
R317  10K  [R0402]  8 24.77 180 bottom
R318  0  [R0402]  93.98 97.28 270 top
R319  10K  [R0402]  57.15 58.34 270 top
R320  10K  [R0402]  68.96 40.39 180 top
R321  4.7K  [R0402]  74.8 40.26 180 top
R322  4.7K  [R0402]  74.8 41.4 180 top
R323  0  [R0402]  74.68 45.34 180 top
R324  0  [R0402]  74.68 44.25 0 top
R325  100K  [R0402]  14.73 54.1 0 top
R326  1K  [R0402]  22.35 45.09 90 top
R327  1K  [R0402]  22.35 49.91 90 top
R328  100K  [R0402]  16.51 44.32 270 top
R329  100K  [R0402]  17.53 48.13 270 top
R330  0  [R0402]  17.53 100.08 0 top
R331  10K  [R0402]  17.02 98.42 270 top
R332  10K  [R0402]  18.16 98.42 90 top
R333  1K  [R0402]  10.79 79.63 0 top
R334  0  [R0402]  8.51 87.88 270 top
R335  0  [R0402]  6.35 83.57 270 top
R336  1  [R0402]  14.99 36.2 270 top
R337  10K  [R0402]  10.41 91.44 0 top
R338  10K  [R0402]  10.41 92.58 180 top
R339  0  [R0402]  16.76 89.15 270 top
R340  0  [R0402]  17.91 89.15 270 top
R341  249  [R1206]  102.87 9.02 90 top
R342  10K  [R0402]  96.9 7.24 90 top
R343  7.5K  [R0402]  78.87 85.45 180 bottom
R344  0  [R0402]  76.33 87.38 90 bottom
R345  10.5K  [R0402]  78.87 87.5 180 bottom
R346  49.9K  [R0402]  14.73 58.93 180 top
R347  100K  [R0402]  12.7 57.15 180 top
R348  49.9K  [R0402]  17.91 52.83 90 top
R349  1K  [R0402]  32.64 31.88 0 top
R350  0  [R0402]  34.29 34.67 270 top
R351  0  [R0402]  104.14 94.87 270 top
R352  10K  [R0402]  38.44 62.61 90 top
R353  10K  [R0402]  37.21 66.8 0 top
R354  1K  [R0402]  23.88 44.7 0 top
R355  10K  [R0402]  58.17 46.86 270 top
R356  10K  [R0402]  39.37 55.88 0 top
R357  10K  [R0402]  52.58 9.14 0 top
R358  0  [R0402]  86.73 26.26 90 top
R359  0  [R0402]  87.88 26.26 90 top
R360  0  [R0402]  99.57 74.45 180 top
R361  0  [R0402]  99.44 53.54 180 top
R362  0  [R0402]  99.57 75.54 0 top
R363  0  [R0402]  99.44 54.61 0 top
R364  0  [R0402]  99.31 35.99 180 top
R365  0  [R0402]  99.31 14.94 180 top
R366  0  [R0402]  99.31 37.08 0 top
R367  0  [R0402]  99.31 16 0 top
R368  10K  [R0402]  112.4 64.32 180 top
R369  10K  [R0402]  112.02 55.92 180 top
R370  10K  [R0402]  112.02 25.84 180 top
R371  10K  [R0402]  112.02 17.41 180 top
R372  0  [R0402]  30.99 49.15 180 top
R373  0  [R0402]  31.62 42.16 0 top
R374  0  [R0402]  30.99 48.01 0 top
R375  0  [R0402]  34.67 42.67 270 top
S1  219-2LPSTR  [SWSML258W264H180]  59.79 6.23 90 top
S2  PTS645VL31-2 LFS  [SWTHRAL295W287H244]  2.54 14.35 270 top
TP1  TESTPAD  [TPSMC30]  39.75 25.02 180 bottom
TP2  TESTPAD  [TPSMC30]  25.91 102.23 180 bottom
TP3  TESTPAD  [TPSMC30]  39.37 28.45 0 top
TP4  TESTPAD  [TPSMC30]  86.49 14.38 180 bottom
TP5  TESTPAD  [TPSMC30]  86.49 35.26 180 bottom
TP6  TESTPAD  [TPSMC30]  66 33.76 0 top
TP7  TESTPAD  [TPSMC30]  57.4 50.8 0 top
TP8  TESTPAD  [TPSMC30]  66 35.36 0 top
TP9  TESTPAD  [TPSMC30]  65.87 12.8 0 top
TP10  TESTPAD  [TPSMC30]  65.87 14.4 0 top
TP11  TESTPAD  [TPSMC30]  86.49 73.77 180 bottom
TP12  TESTPAD  [TPSMC30]  86.49 52.89 180 bottom
TP13  TESTPAD  [TPSMC40]  95.25 101.22 0 top
TP14  TESTPAD  [TPSMC30]  66 72.27 0 top
TP15  TESTPAD  [TPSMC30]  66 73.87 0 top
TP16  TESTPAD  [TPSMC30]  65.87 51.31 0 top
TP17  TESTPAD  [TPSMC30]  65.87 52.91 0 top
TP18  TESTPAD  [TPSMC30]  57.48 49.41 0 top
TP19  TESTPAD  [TPSMC30]  50.29 31.37 180 bottom
TP20  TESTPAD  [TPSMC30]  56.64 13.72 90 bottom
TP21  TESTPAD  [TPSMC30]  61.98 70.48 0 top
TP22  TESTPAD  [TPSMC30]  57.53 21.08 90 bottom
TP23  TESTPAD  [TPSMC30]  56.97 16.64 0 top
TP24  TESTPAD  [TPSMC30]  57.28 62.74 180 top
TP25  TESTPAD  [TPSMC30]  66.09 58.12 180 top
TP26  TESTPAD  [TPSMC30]  39.24 10.92 0 top
TP27  TESTPAD  [TPSMC30]  47.51 32.72 90 bottom
TP28  TESTPAD  [TPSMC30]  37.85 10.92 180 bottom
TP29  TESTPAD  [TPSMC30]  77.22 87.63 0 top
TP30  TESTPAD  [TPSMC30]  38.61 9.14 180 bottom
TP31  TESTPAD  [TPSMC30]  72.77 91.19 0 top
TP32  TESTPAD  [TPSMC30]  90.42 93.73 0 top
TP33  TESTPAD  [TPSMC30]  11.68 25.15 270 top
TP34  TESTPAD  [TPSMC30]  41.4 9.91 180 bottom
TP35  TESTPAD  [TPSMC30]  9.66 25.12 270 top
TP36  TESTPAD  [TPSMC40]  11.3 3.81 0 top
TP37  TESTPAD  [TPSMC40]  52.83 93.98 0 top
TP38  TESTPAD  [TPSMC40]  104.52 3.94 0 top
TP39  TESTPAD  [TPSMC30]  37.85 43.18 0 top
TP40  TESTPAD  [TPSMC30]  57.53 22.61 180 bottom
TP41  TESTPAD  [TPSMC30]  38.23 46.23 0 top
TP42  TESTPAD  [TPSMC30]  36.58 46.23 0 top
TP43  TESTPAD  [TPSMC30]  38.23 47.75 0 top
TP44  TESTPAD  [TPSMC30]  36.58 47.75 0 top
TP45  TESTPAD  [TPSMC40]  9.14 43.81 0 top
TP46  TESTPAD  [TPSMC40]  28.83 71.88 270 top
TP47  TESTPAD  [TPSMC40]  26.04 75.18 0 top
TP48  TESTPAD  [TPSMC40]  24 39.75 0 top
TP49  TESTPAD  [TPSMC40]  38.86 101.98 0 top
TP50  TESTPAD  [TPSMC40]  41.28 87.88 0 top
TP51  TESTPAD  [TPSMC40]  11.94 17.4 180 top
TP52  TESTPAD  [TPSMC40]  50.67 101.98 0 top
TP53  TESTPAD  [TPSMC40]  50.42 87.25 0 top
TP54  TESTPAD  [TPSMC40]  30.34 66.14 90 top
TP55  TESTPAD  [TPSMC40]  34.67 60.07 0 top
TP56  TESTPAD  [TPSMC30]  31.01 13.84 0 top
TP57  TESTPAD  [TPSMC30]  92.44 96.19 270 top
TP58  TESTPAD  [TPSMC30]  72.77 100.08 0 top
TP59  TESTPAD  [TPSMC30]  102.36 94.61 0 top
TP60  TESTPAD  [TPSMC30]  77.85 39.75 180 bottom
TP61  TESTPAD  [TPSMC30]  77.85 38.23 180 bottom
TP62  TESTPAD  [TPSMC40]  9.53 22.86 0 top
TP63  TESTPAD  [TPSMC40]  11.3 22.86 0 top
TP64  TESTPAD  [TPSMC30]  76.2 39.75 180 bottom
TP65  TESTPAD  [TPSMC30]  76.2 38.23 180 bottom
TP66  TESTPAD  [TPSMC30]  37.47 28.32 0 top
TP67  TESTPAD  [TPSMC30]  46.1 32 180 bottom
TP68  TESTPAD  [TPSMC30]  49.66 30.86 0 top
TP69  TESTPAD  [TPSMC30]  49.02 31.37 180 bottom
TP70  TESTPAD  [TPSMC40]  11.18 48.13 0 top
TP71  TESTPAD  [TPSMC30]  56.77 24.51 180 bottom
U1  CYUSB3014-BZXI  [BGA121_A]  45.5 20.79 0 top
U2  W25Q64JVSSIM  [SO8_A]  57.79 36.45 90 top
U3  SN74AUP1G17DBVR  [SOT23-5L]  9.53 72.26 0 top
U4  LT3092ETS8#TRMPBF  [TSOT-8]  96.39 28.19 0 top
U5  LT3092ETS8#TRMPBF  [TSOT-8]  96.27 19.94 0 top
U6  ADA4945-1ACPZ-R7  [QFN16_3X3_PAD1_6X1_6]  74.04 13.6 90 top
U7  LT3092ETS8#TRMPBF  [TSOT-8]  96.39 66.71 0 top
U8  LT3092ETS8#TRMPBF  [TSOT-8]  96.27 58.45 0 top
U9  ADA4945-1ACPZ-R7  [QFN16_3X3_PAD1_6X1_6]  74.17 73.07 90 top
U10  ADA4945-1ACPZ-R7  [QFN16_3X3_PAD1_6X1_6]  74.04 52.11 90 top
U11  ADP7142ACPZN  [DFN6_2X2_PAD1_6X1]  32.51 76.33 0 top
U12  LTC4332HUFD#PBF  [QFN20_5X4_PAD3_65X2_65]  41.4 67.94 270 top
U13  LT8330EDDB#TRMPBF  [DFN8_3X2_PAD2_15X0_56]  18.16 76.71 0 top
U14  ADP1708ACPZ  [QFN8_3X3_PAD1_75X1_45-1]  14.99 14.48 90 top
U15  ADP5071AREZ  [TSSOP20_PAD4_2X3]  28.57 93.09 180 top
U16  AD5686RBCPZ-RL7  [QFN16_3X3_PAD1_6X1_6]  59.7 46.98 270 bottom
U17  ADR4540BRZ  [SO8]  54.99 71.12 270 top
U18  AD7768-4BSTZ  [LQFP64]  45.85 48.39 180 top
U19  AD9833BRMZ  [RM10]  76.84 83.95 270 top
U20  AD5543CRMZ  [MSOP8]  76.84 94.36 90 top
U21  ADA4945-1ACPZ-R7  [QFN16_3X3_PAD1_6X1_6]  74.17 34.56 90 top
U22  ADG5436BCPZ  [QFN16_4X4_PAD2_6X2_6]  95.04 72.84 90 top
U23  ADP7118AUJZ-5.0  [TSOT-5]  48.13 99.06 270 top
U24  ADP7182ACPZN  [DFN6_2X2_PAD1_6X1]  48.77 91.19 90 top
U25  ADG5401BRMZ  [MSOP8]  107.95 64.64 270 top
U26  ADP1708ACPZ  [QFN8_3X3_PAD1_75X1_45-1]  28.07 15.11 270 top
U27  ADG5436BCPZ  [QFN16_4X4_PAD2_6X2_6]  94.91 51.89 90 top
U28  ADG5436BCPZ  [QFN16_4X4_PAD2_6X2_6]  95.04 34.33 90 top
U29  ADG5436BCPZ  [QFN16_4X4_PAD2_6X2_6]  94.91 13.38 90 top
U30  LTC3112IFE#PBF  [TSSOP20_PAD4_95X2_74]  20.76 63.72 90 top
U31  ADP7118AUJZ-5.0  [TSOT-5]  33.48 57.19 270 top
U32  ADG1219BRJZ  [SOT23_8]  89.28 96.39 270 top
U33  SN74AUP1G17DBVR  [SOT23-5L]  11.3 85.72 180 top
U34  ADG5401BRMZ  [MSOP8]  107.7 56.25 270 top
U35  CBTU02043HEJ  [HUQFN16]  19.3 28.07 90 bottom
U36  PTN5150AHXMP  [XFQFN12]  10.7 22.99 180 bottom
U37  ADG839YKSZ-500RL7  [SC70-6]  10.92 89.53 90 top
U38  SN74AUP1G17DBVR  [SOT23-5L]  3.43 84.45 270 top
U39  MAX14595ETA+T  [DFN8_2X2]  71.75 41.4 270 top
U40  MAX7312AAG+  [SSOP24-2]  75.06 46.35 0 bottom
U41  SN74AUP1G17DBVR  [SOT23-5L]  16 85.72 0 top
U42  74AUP1G125GW,125  [SOT353]  32.26 34.29 0 top
U43  ADG5401BRMZ  [MSOP8]  107.7 26.16 270 top
U44  ADG5401BRMZ  [MSOP8]  107.7 17.73 270 top
VREF  TESTPAD  [TPSMC30]  47.7 59.85 0 top
Y1  19.2MEGHZ  [YSML79W63H20]  33.2 29.53 90 top
Y2  32.768KHZ  [YSML98W79H35]  31.11 24.51 0 top
Y3  25MEGHZ  [YSML197W126H51]  28.19 43.43 270 top
Y4  25MEGHZ  [YSML197W126H51]  67.56 83.44 270 top
Y5  32.768MEGHZ  [YSML98W79H35]  34.04 45.72 270 top
Y6  10MEGHZ  [XSM4PL275W200H55]  12.19 96.65 180 top

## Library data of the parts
A1-A4 A16-A19 = ADA4099_1: User Part Number: UPN; Tolerance: N/A; alternate symbols: (); part number: ADA4099_1_SM-ADA4099-1HUJZ,E041322,TSOT23_6; tolerance: N/A
A5 A7 A8 A14 = ADA4522_1: Tolerance: N/A; User Part Number: UPN; alternate symbols: (); part number: ADA4522_1_SM-ADA4522-1ARMZ,E038781,MSOP8; tolerance: N/A
A6 A9 A15 = ADA4807_1: User Part Number: UPN; Tolerance: N/A; alternate symbols: (); part number: ADA4807_1_SM-ADA4807-1ARJZ,E031217,SOT23_6-2; tolerance: N/A
A10-A13 = ADLTC6910_X: User Part Number: UPN; Tolerance: N/A; alternate symbols: (); part number: ADLTC6910_X_SM-LTC6910-1HTS8#TRMPBF,E055522,TSOT-8; tolerance: N/A
C1 C12-C14 C19 C22 C24 C35 C36 C47 C48 C67 C68 C79 C80 C90 C99 C101-C103 C132 C134-C136 C139-C142 C144 C145 C147 C151 C156 C158 C159 C161-C163 C165 C167 C169 C172 C174 C176 C177 C180 C182 C186 C187 C189 C191 C194 C198-C200 C203 C205-C207 C210 C213 C219 C220 C229 C230 C233-C235 C238 C239 C241 C244 C245 C255 C256 C268 C270 C273-C275 C281-C283 C285 C287 C289 C294 C299-C302 = CAP: User Part Number: UPN; Tolerance: 10; alternate symbols: (C0402L); part number: CAP_SM-0.1UF,16V,10,E033898,C0402; tolerance: 10
C2 C106 C247 C257 C278 C280 = CAP: User Part Number: UPN; Tolerance: 10; alternate symbols: (C0603L); part number: CAP_SM-4.7UF,35V,10,E039350,C0603; tolerance: 10
C3 C108 C248 C258-C260 = CAP: User Part Number: UPN; Tolerance: 10; alternate symbols: (C0603L); part number: CAP_SM-1UF,50V,10,E032711,C0603; tolerance: 10
C4-C11 C43-C46 C75-C78 C92 C240 C242 = CAP: User Part Number: UPN; Tolerance: 1; alternate symbols: (C0402L); part number: CAP_SM-1000PF,50V,1,E032072,C0402; tolerance: 1
C15 C27 C28 C59 C60 C105 C179 C181 C183 C188 C190 C192 C214 C215 C236 C237 C263-C266 C291 C307-C310 = CAP: User Part Number: UPN; Tolerance: 20; alternate symbols: (C0402L); part number: CAP_SM-10UF,10V,20,E020928,C0402; tolerance: 20
C16 C37 C38 C49 C50 C69 C70 C81 C82 C98 C100 C113 C133 C137 C143 C160 C164 C166 C168 C171 C173 C175 C184 C218 C226 C228 C231 C232 C246 C269 C276 C286 C290 C303-C306 = CAP: User Part Number: UPN; Tolerance: 20; alternate symbols: (C0402L); part number: CAP_SM-1UF,6.3V,20,E030484,C0402; tolerance: 20
C17 C93 C94 C97 C122 C123 C126 C128 C152 C208 C209 C225 C227 C277 = CAP: User Part Number: UPN; Tolerance: 10; alternate symbols: (C0603L); part number: CAP_SM-4.7UF,16V,10,E020112,C0603; tolerance: 10
C18 C119 C120 C131 C149 C150 C153 C157 C195 = CAP: User Part Number: UPN; Tolerance: 20; alternate symbols: (C0603L); part number: CAP_SM-22UF,10V,20,E022680,C0603; tolerance: 20
C20 C21 C23 C138 C148 C155 C170 C178 C197 C201 C267 C288 = CAP: User Part Number: UPN; Tolerance: 10; alternate symbols: (C0402L); part number: CAP_SM-0.01UF,16V,10,E019652,C0402; tolerance: 10
C25 C26 C29-C32 C57 C58 C61-C64 C89 C107 C114 C121 C124 C125 C127 C211 C212 C261 C262 C295 C296 = CAP: User Part Number: UPN; Tolerance: 10; alternate symbols: (C0402L); part number: CAP_SM-0.1UF,50V,10,E034665,C0402; tolerance: 10
C33 C34 C65 C66 = CAP: User Part Number: UPN; Tolerance: 5; alternate symbols: (C0402L); part number: CAP_SM-68PF,50V,5,E033338,C0402; tolerance: 5
C39-C42 C51 C52 C71-C74 C83 C84 C185 C216 = CAP: User Part Number: UPN; Tolerance: 5; alternate symbols: (C0603L); part number: CAP_SM-1800PF,50V,5,E011705,C0603; tolerance: 5
C53-C56 C85-C88 = CAP: User Part Number: UPN; Tolerance: 1; alternate symbols: (C0603L); part number: CAP_SM-100PF,100V,1,E023659,C0603; tolerance: 1
C91 C96 C196 C243 = CAP: Tolerance: 10; User Part Number: UPN; alternate symbols: (); part number: CAP_SM-2.2UF,50V,10,E016729,C0805H60; tolerance: 10
C95 = CAP: User Part Number: UPN; Tolerance: 10; alternate symbols: (C0402L); part number: CAP_SM-0.22UF,50V,10,E038241,C0402; tolerance: 10
C104 C115-C118 C129 C130 C146 C217 C249 C250 C279 C284 C297 C298 = CAP: User Part Number: UPN; Tolerance: 20; alternate symbols: (C0603L); part number: CAP_SM-10UF,35V,20,E026762,C0603; tolerance: 20
C109 C111 = CAP: User Part Number: UPN; Tolerance: 5; alternate symbols: (C0402L); part number: CAP_SM-1200PF,25V,5,E012597,C0402; tolerance: 5
C110 C223 = CAP: User Part Number: UPN; Tolerance: 5; alternate symbols: (C0402L); part number: CAP_SM-47PF,50V,5,E011821,C0402; tolerance: 5
C112 = CAP: User Part Number: UPN; Tolerance: 10; alternate symbols: (C0603L); part number: CAP_SM-6800PF,16V,10,E042623,C0603; tolerance: 10
C154 = CAP: User Part Number: UPN; Tolerance: 10; alternate symbols: (C0603L); part number: CAP_SM-0.47UF,35V,10,E019601,C0603; tolerance: 10
C193 = CAP: User Part Number: UPN; Tolerance: 0.1pF; alternate symbols: (C0402L); part number: CAP_SM-5.6PF,25V,0.1PF,E011114,C0402; tolerance: 0.1pF
C202 C204 = CAP: User Part Number: UPN; Tolerance: 5; alternate symbols: (C0402L); part number: CAP_SM-15PF,50V,5,E035213,C0402; tolerance: 5
C221 = CAP: User Part Number: UPN; Tolerance: 5; alternate symbols: (C0402L); part number: CAP_SM-680PF,50V,5,E007981,C0402; tolerance: 5
C222 = CAP: User Part Number: UPN; Tolerance: 5; alternate symbols: (C0402L); part number: CAP_SM-22PF,16V,5,E042650,C0402; tolerance: 5
C224 = CAP: Tolerance: 10; User Part Number: UPN; alternate symbols: (); part number: CAP_SM-47UF,10V,10,E011546,C1210-2; tolerance: 10
C251-C254 C271 C272 = CAP: User Part Number: UPN; Tolerance: 10; alternate symbols: (C0402L); part number: CAP_SM-0.1UF,16V,10,E033898,C0402; tolerance: 10; signal model: CAP_SM-0.1UF_16V_10_E033898_C0402-C0402_0.1uF
C292 = CAP: User Part Number: UPN; Tolerance: 0.5PF; alternate symbols: (C0402L); part number: CAP_SM-10PF,50V,0.5PF,E041472,C0402; tolerance: 0.5PF
C293 = CAPP: Tolerance: 10; User Part Number: UPN; alternate symbols: (); part number: CAPP_SM-100UF,16V,10,E000720,C7343; tolerance: 10
C311 = CAP: User Part Number: UPN; Tolerance: 0.1pF; alternate symbols: (C0402L); part number: CAP_SM-4.7PF,25V,0.1PF,E011139,C0402; tolerance: 0.1pF
CAP2.5 TP1-TP12 TP14-TP35 TP39-TP44 TP56-TP61 TP64-TP69 TP71 VREF = NCTESTPAD: Tolerance: N/A; User Part Number: UPN; alternate symbols: (); part number: NCTESTPAD_SM-TESTPAD,E012884,TPSMC30; tolerance: N/A
D1 = DIOSCHOTTKY: Tolerance: N/A; User Part Number: UPN; alternate symbols: (); part number: DIOSCHOTTKY_SM-PMEG3010BEA,115,30V,N/A,E014012,SOD323; tolerance: N/A
D2 D3 = DIOSCHOTTKY: User Part Number: UPN; Tolerance: N/A; alternate symbols: (); part number: DIOSCHOTTKY_SM-MBR130LSFT1G,30V,N/A,E016634,SOD123FL; tolerance: N/A
D4 = DIO4P_V11: User Part Number: UPN; Tolerance: N/A; alternate symbols: (); part number: DIO4P_V11_SM-BAV99QAZ,90V,N/A,E034938,SOT1215; tolerance: N/A
D5 D12-D17 D19 D20 = DIOTVS_BIDIR: Tolerance: N/A; User Part Number: UPN; alternate symbols: (); part number: DIOTVS_BIDIR_SM-D5V0H1B2LP-7B,5.5V,N/A,E055210,DFN2_1X0_6_NP_A; tolerance: N/A
D6 D8 = DIOSCHOTTKY: Tolerance: N/A; User Part Number: UPN; alternate symbols: (); part number: DIOSCHOTTKY_SM-BAT54WS-E3,30V,N/A,E006531,SOD323-3; tolerance: N/A
D7 D9-D11 = DIO_V3: User Part Number: UPN; Tolerance: N/A; alternate symbols: (); part number: DIO_V3_SM-SMAJ40CA-TR,40V,N/A,E038294,DO214AC_C; tolerance: N/A
D18 = DIOSCHOTTKY: User Part Number: UPN; Tolerance: N/A; alternate symbols: (); part number: DIOSCHOTTKY_SM-PMEG3050EP,115,30V,N/A,E038321,SOD128; tolerance: N/A
DS1 = DIOLED: User Part Number: UPN; Tolerance: N/A; alternate symbols: (); part number: DIOLED_SM-SML-P11MTT86R,N/A,N/A,E014445,LED0402; tolerance: N/A
DS2 = DIOLED: User Part Number: UPN; Tolerance: N/A; alternate symbols: (); part number: DIOLED_SM-SML-P11VTT86,N/A,N/A,E019415,LED0402; tolerance: N/A
E1 E5 E10-E17 = FERRITE: User Part Number: UPN; Tolerance: 25; alternate symbols: (L0805L); part number: FERRITE_SM-220 OHM AT 100MEGHZ,25,E056159,L0805; tolerance: 25
E2-E4 = FERRITE: User Part Number: UPN; Tolerance: 25; alternate symbols: (L0603L); part number: FERRITE_SM-1000OHM AT 100MEGHZ,25,E027309,L0603; tolerance: 25
E6-E9 = FERRITE: User Part Number: UPN; Tolerance: 25; alternate symbols: (L0805L); part number: FERRITE_SM-600OHM AT 100MEGHZ,25,E022193,L0805; tolerance: 25
F1 = FSFUSE: Tolerance: N/A; User Part Number: UPN; alternate symbols: (); part number: FSFUSE_SM-2A,6V,E035645,F1206H46; tolerance: N/A
FL1 FL2 = FLTRPCM15P: User Part Number: UPN; Tolerance: N/A; alternate symbols: (); part number: FLTRPCM15P_SM-PCMF3USB30Z,E055153,WLCSP15H22; tolerance: N/A
J1-J4 = CNBNC5P: User Part Number: UPN; Tolerance: N/A; alternate symbols: (); part number: CNBNC5P_TH-SMA-J-P-H-RA-TH1,E024544,CNSMARAL594W276H393; tolerance: N/A
